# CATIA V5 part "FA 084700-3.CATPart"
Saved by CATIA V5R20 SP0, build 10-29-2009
Part number: FA 084700-3
Revision: ANY
Definition: UNKNOWN
Nomenclature: FA 084700-3
Source: Unknown
Bounding box of the stored display mesh (mm): x -2.687 to 2.687, y -2.475 to 2.475, z -2.5 to 2.5
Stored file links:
  C:\Users\Utente\Desktop\IO LAVORO\3D X SITO CF\CUMSA\3D files FA\FA 0847SF\FA 084700-3.CATPart

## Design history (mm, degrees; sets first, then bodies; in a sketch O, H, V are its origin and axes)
Body1 "Chaflán4" (main body)
  Solid1: solid without history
